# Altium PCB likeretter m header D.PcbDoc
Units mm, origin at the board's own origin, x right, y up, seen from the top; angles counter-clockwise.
Board outline 55.88 x 55.25 mm, 2 copper layers (Top Layer, Bottom Layer); 16 components, 12 nets, 56 pads, 0 vias.
Unrouted connection lines stored in the file: 3.
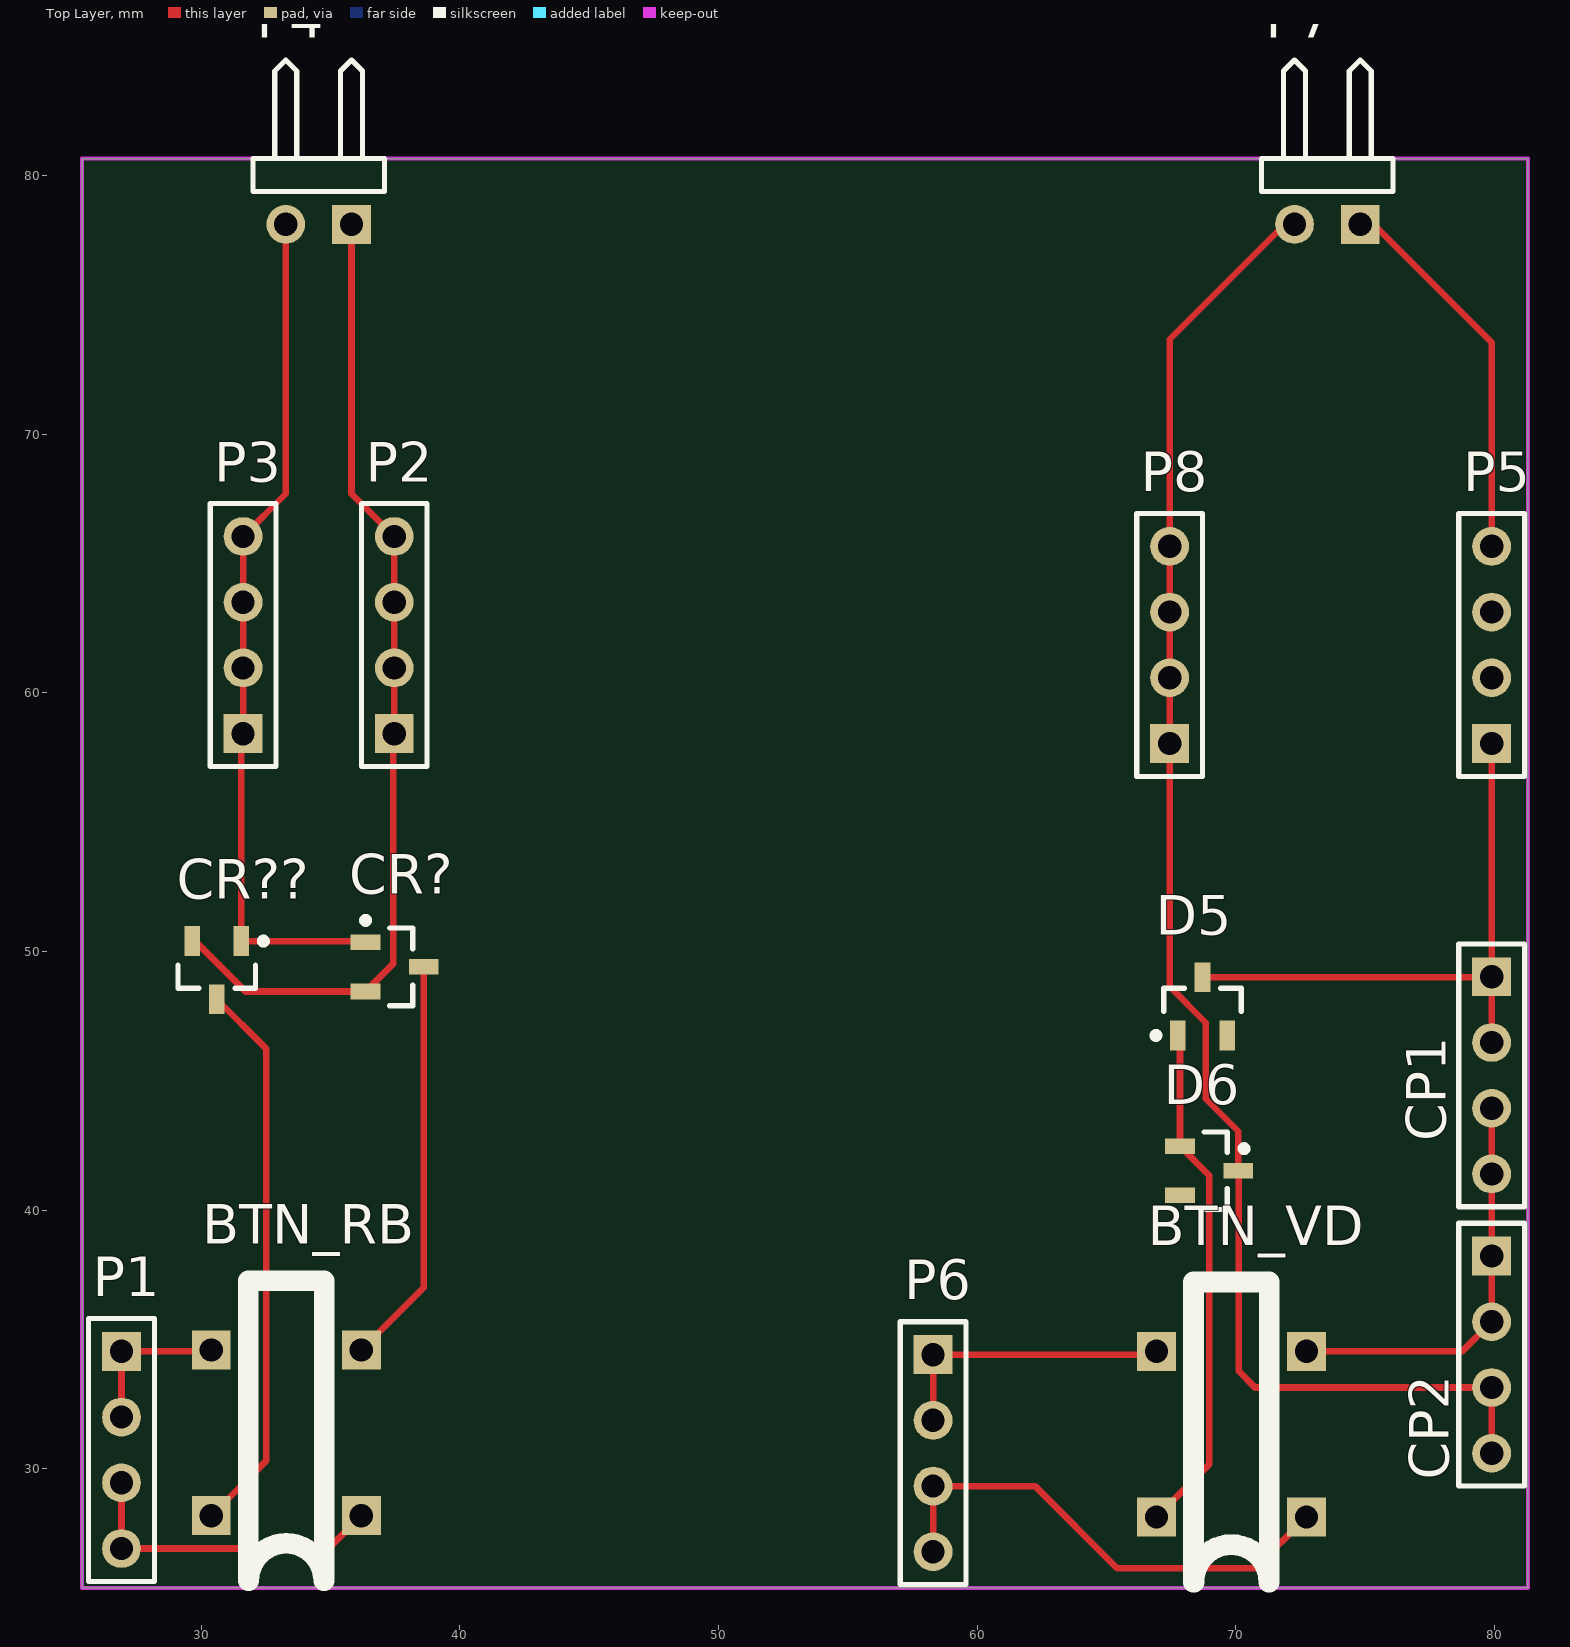
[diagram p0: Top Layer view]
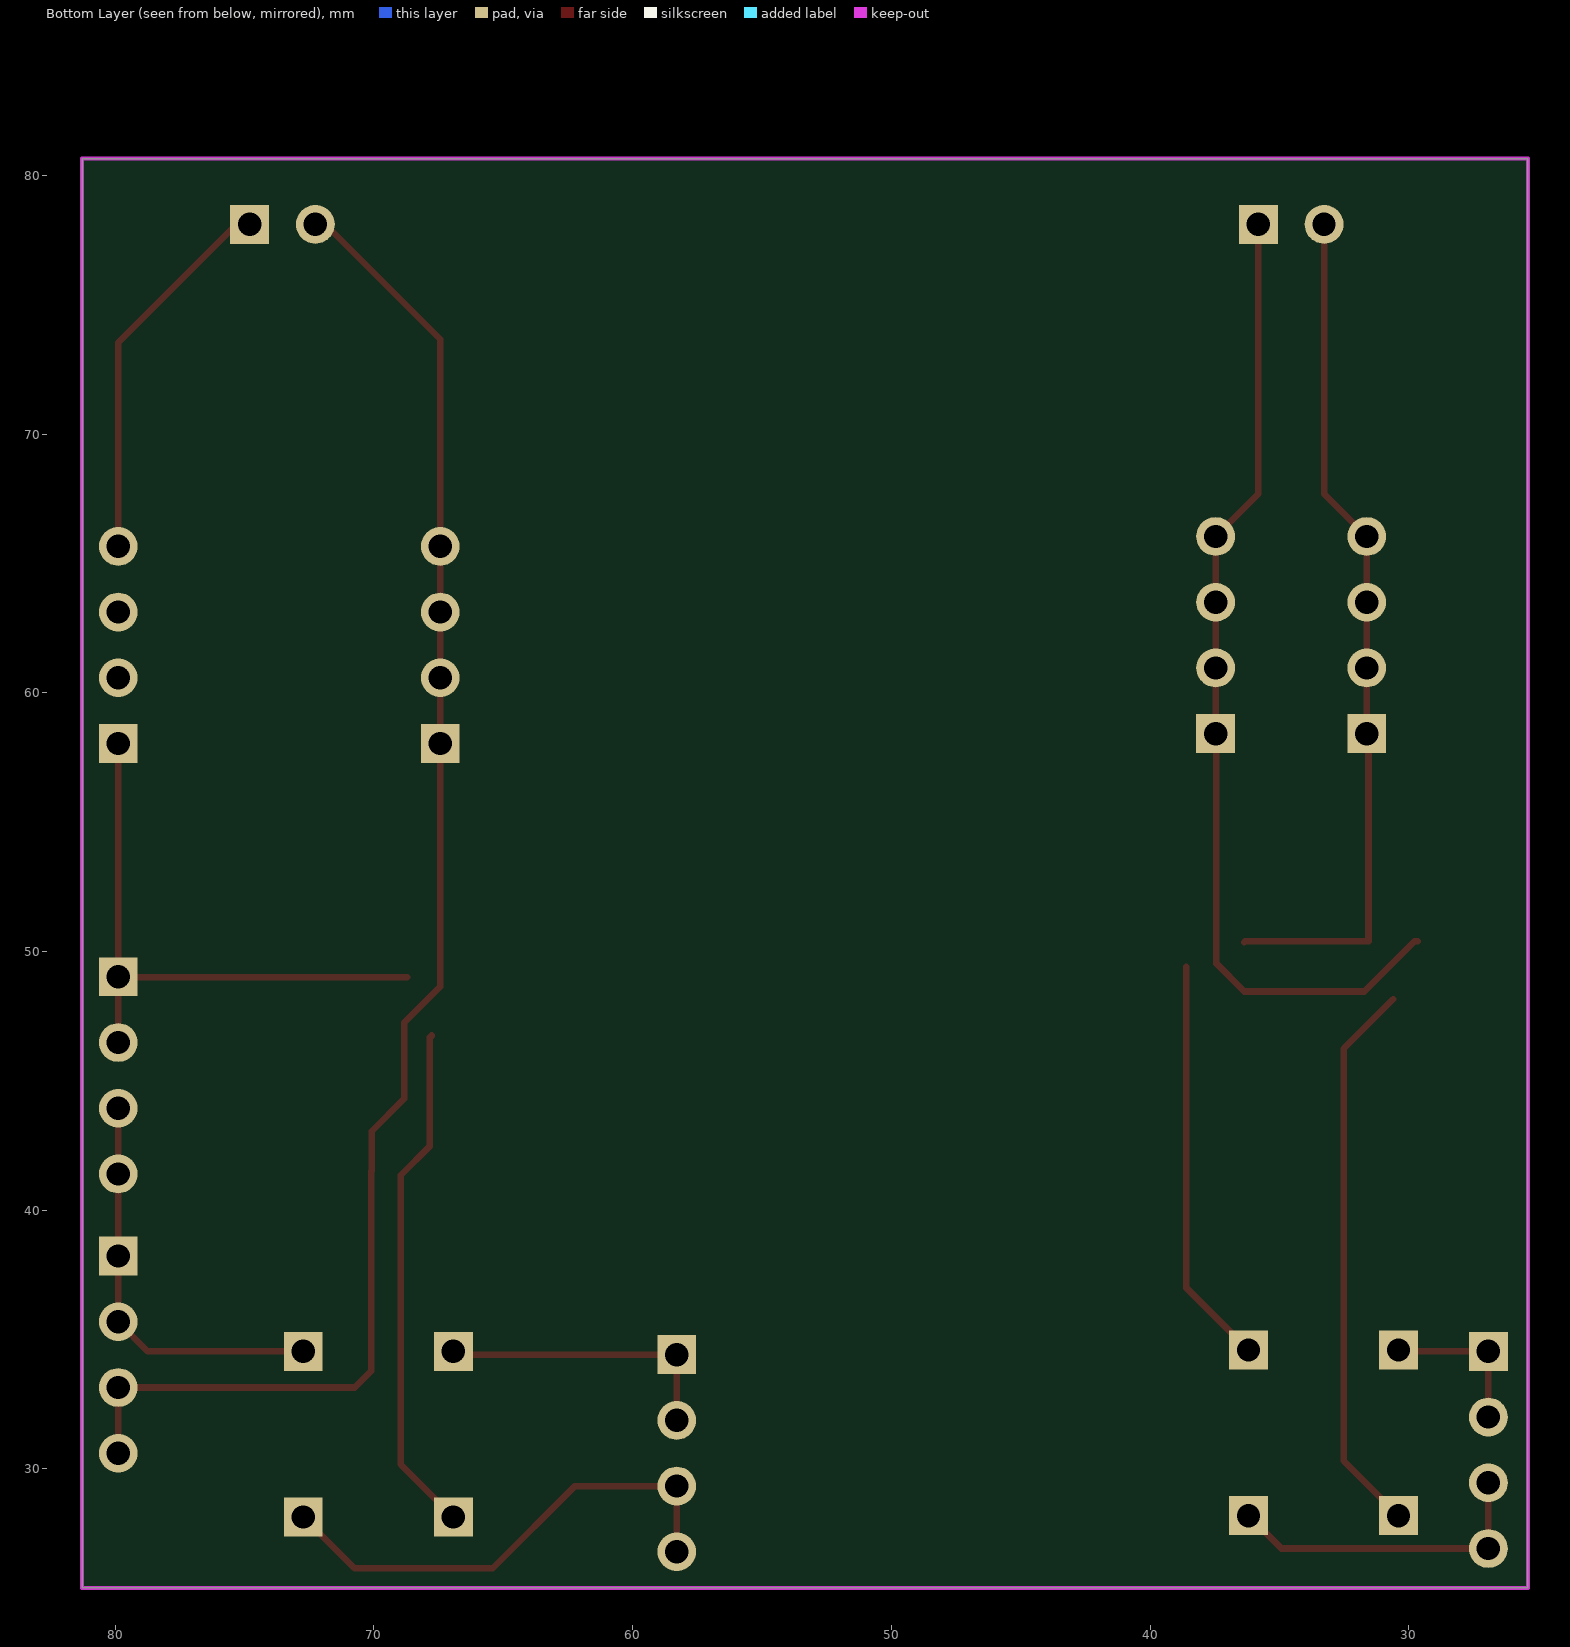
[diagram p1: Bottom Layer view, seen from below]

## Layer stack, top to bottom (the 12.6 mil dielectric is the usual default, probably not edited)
Top Solder: solder mask 0.0102, Solder Resist, Dk 3.5
Top Layer: signal copper 0.0356
Dielectric 1: dielectric 0.32, FR-4, Dk 4.8
Bottom Layer: signal copper 0.0356
Bottom Solder: solder mask 0.0102, Solder Resist, Dk 3.5

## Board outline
25.4,25.4 81.28,25.4 81.28,80.645 25.4,80.645

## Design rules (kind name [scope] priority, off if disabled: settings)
Clearance [All] p1: gap=0.254 ignorepadtopadclearanceinfootprint=FALSE except(0: Arc-Hole Track-Hole SMDPad-Hole THPad-Hole Via-Hole Fill-Hole Poly-Hole Region-Hole Text-Hole)
PolygonConnect [All] p1: connectstyle=Relief reliefconductorwidth=0.254 reliefentries=4 polygonreliefangle="90 Angle" airgapwidth=0.254
RoutingVias [All] p1: holewidth=0.711 width=1.27 viastyle="Through Hole" minholewidth=0.711 minwidth=1.27 maxholewidth=0.711 maxwidth=1.27
SolderMaskExpansion [All] p1: expansion=0.102
Width [All] p1: maxlimit=0.254 minlimit=0.254 preferedwidth=0.254
30 further rules are at their usual default settings.

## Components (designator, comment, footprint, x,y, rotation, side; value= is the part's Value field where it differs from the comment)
BTN_RB "ZF_button" ZF-button 30.395,28.194 r90 top
BTN_VD "ZF_button" ZF-button 66.929,28.144 r90 top
CP1 "Cap Header 1" HDR1X4 79.883,49.022 r270 top
CP2 "Cap Header 2" HDR1X4 79.883,38.227 r270 top
CR? "1KAB100E" SOT-23_N 37.483,49.403 r0 top
CR?? "1KAB100E" SOT-23_N 30.607,49.276 r270 top
D5 "Diode 1N4004" SOT-23_N 68.707,47.879 r90 top
D6 "Diode 1N4004" SOT23_N 68.961,41.529 r0 top
P1 "Header 4" HDR1X4 26.924,34.544 r270 top
P2 "Header 4" HDR1X4 37.465,58.42 r90 top
P3 "Header 3" HDR1X4 31.623,58.42 r90 top
P4 "Header 2H" HDR1X2H 35.814,78.105 r180 top
P5 "Header 4" HDR1X4 79.883,58.039 r90 top
P6 "Header 4" HDR1X4 58.293,34.417 r270 top
P7 "Header 2H" HDR1X2H 74.803,78.105 r180 top
P8 "Header 4" HDR1X4 67.437,58.039 r90 top

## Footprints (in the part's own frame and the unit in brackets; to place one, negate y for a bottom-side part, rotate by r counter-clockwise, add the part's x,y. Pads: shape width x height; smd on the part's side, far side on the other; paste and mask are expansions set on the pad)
HDR1X2H [mm] "Connector; Header; 2 Position; Right Angle"
  rect 1.5x1.5 hole 0.9: 1(0,0)
  round 1.5 hole 0.9: 2(2.54,0)
  silkscreen extent -1.27,-6.35 3.81,-1.27
HDR1X4 [mm] "Connector; Header; 4 Position"
  rect 1.5x1.5 hole 0.9: 1(0,0)
  round 1.5 hole 0.9: 2(2.54,0) 3(5.08,0) 4(7.62,0)
  silkscreen extent -1.27,-1.27 8.89,1.27
SOT23_N [mm] "SOT23, 3-Leads, Body 2.9x1.3mm, Pitch 0.95mm, Lead Span 2.3mm - Reverse Pinning, IPC Medium Density"
  rect 1.15x0.6 smd: 1(1.125,0) 2(-1.125,-0.95) 3(-1.125,0.95)
  silkscreen extent -0.2,-1.5 1.48,1.5, body extent -0.7,-1.5 0.7,1.5, height 1.1
SOT-23_N [mm] "SOT23, 3-Leads, Body 2.9x1.3mm, Pitch 0.95mm, Lead Span 2.5mm, IPC Medium Density"
  rect 1.15x0.6 smd: 1(-1.125,0.95) 2(-1.125,-0.95) 3(1.125,0)
  silkscreen extent -1.25,-1.5 0.7,1.92, body extent -0.7,-1.5 0.7,1.5, height 1.1
ZF-button [mm]
  rect 1.5x1.5 hole 0.9: 1(0,0) 2(0,-5.8) 3(6.4,-5.8) 4(6.4,0)
  silkscreen extent -2.52,-4.36 9.08,-1.43

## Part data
CP1 CP2 P3: library part "Header 4", "Header, 4-Pin"
CR? CR??: "1.2 Amp Rectifier Bridge"
D5 D6: "1 Amp General Purpose Rectifier"
P1 P2 P5 P6 P8: "Header, 4-Pin"
P4 P7: "Header, 2-Pin, Right Angle"

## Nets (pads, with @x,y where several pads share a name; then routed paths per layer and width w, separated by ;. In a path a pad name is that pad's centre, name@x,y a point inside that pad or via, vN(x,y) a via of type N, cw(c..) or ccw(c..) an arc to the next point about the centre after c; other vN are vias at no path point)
NetBTN_RB_1: BTN_RB.1 CR??.3 | length 21.6
  Top Layer w0.254: BTN_RB.1 32.512,30.311 32.512,46.246 CR??.3
NetBTN_RB_2: BTN_RB.2 P1.3 P1.4 | length 12.3
  Top Layer w0.254: P1.3 P1.4 34.925,26.924 BTN_RB.2
NetBTN_RB_3: BTN_RB.3 CR?.3 | length 15.8
  Top Layer w0.254: BTN_RB.3 38.608,37.007 CR?.3
NetBTN_RB_4: BTN_RB.4 P1.1 P1.2 | length 6
  Top Layer w0.254: P1.2 P1.1 30.345,34.544 BTN_RB.4
NetBTN_VD_1: BTN_VD.1 D5.1 D6.3 | length 20
  Top Layer w0.254: BTN_VD.1 68.961,30.176 68.961,41.354 D6.3 67.836,46.675 D5.1
NetBTN_VD_2: BTN_VD.2 P6.3 P6.4 | length 19.1
  Top Layer w0.254: P6.4 P6.3 62.23,29.337 65.405,26.162 70.747,26.162 BTN_VD.2
NetBTN_VD_3: BTN_VD.3 CP1.3 CP1.4 CP2.1 CP2.2 | length 15.9
  Top Layer w0.254: BTN_VD.3 78.74,34.544 CP2.2 CP2.1 CP1.4 CP1.3
NetBTN_VD_4: BTN_VD.4 P6.1 P6.2 | length 11.2
  Top Layer w0.254: P6.2 P6.1 66.802,34.417 BTN_VD.4
NetCP1_1: CP1.1 CP1.2 D5.3 P5.1 P5.2 P5.3 P5.4 P7.1 | length 37.6
  Top Layer w0.254: D5.3 79.865,49.004 CP1.1 ; P7.1 75.311,78.105 79.883,73.533 P5.4 ; CP1.2 CP1.1 ; P5.1 CP1.1
NetCP2_3: CP2.3 CP2.4 D6.1 P7.2 P8.1 P8.2 P8.3 P8.4 | length 60.2
  Top Layer w0.254: P7.2 71.882,78.105 67.437,73.66 P8.4 P8.3 P8.2 P8.1 67.437,48.641 68.834,47.244 68.834,44.305 70.086,43.053 D6.1 70.104,41.511 70.104,33.782 70.739,33.147 CP2.3 CP2.4
NetCR?_1: CR?.1 CR??.1 P3.1 P3.2 P3.3 P3.4 P4.2 | length 33.2
  Top Layer w0.254: P4.2 33.274,67.691 P3.4 P3.3 P3.2 P3.1 31.557,58.354 CR??.1 36.31,50.401 CR?.1
NetCR?_2: CR?.2 CR??.2 P2.1 P2.2 P2.3 P2.4 P4.1 | length 38.3
  Top Layer w0.254: CR??.2 29.771,50.401 31.719,48.453 CR?.2 37.435,49.53 37.435,58.39 P2.1 P2.2 P2.3 P2.4 35.814,67.691 P4.1
pads on no net: D5.2 D6.2

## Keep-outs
Keep-Out Layer:
  the board outline again, w0.152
